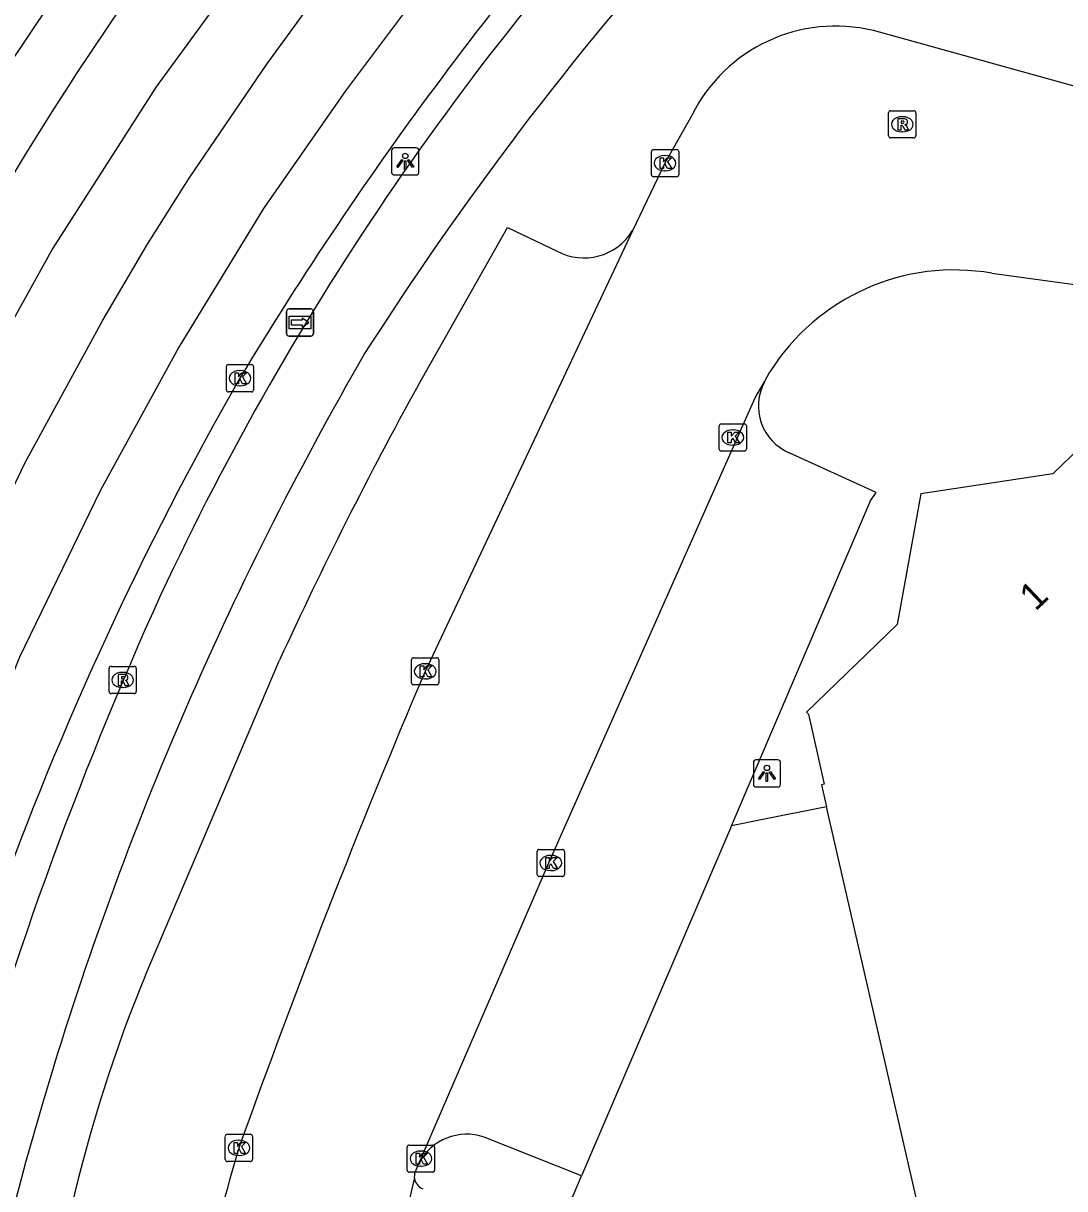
# Model space of a CAD drawing. Extents: x 160676 to 161153, y 383244 to 383713.
# Drawn here: x 160695.65 to 160733.93, y 383532.99 to 383575.83 of the extents above; entities that cross this region are included whole.
import ezdxf

# ---------------------------------------------------------------- set-up
doc = ezdxf.new("R2010")
doc.units = 0
for name, color, linetype in [('IMGEO_Fietspad_gesloten', 7, 'Continuous'), ('IMGEO_Kolk', 7, 'Continuous'), ('IMGEO_Lichtpunt', 7, 'Continuous'), ('IMGEO_Pand', 7, 'Continuous'), ('IMGEO_Pand_nummerreeks', 7, 'Continuous'), ('IMGEO_Parkeervlak_open', 7, 'Continuous'), ('IMGEO_Rijbaan_lokaal_gesloten', 7, 'Continuous'), ('IMGEO_Rijbaan_lokaal_open', 7, 'Continuous'), ('IMGEO_Rioolput', 7, 'Continuous'), ('IMGEO_Voetpad_open', 7, 'Continuous'), ('IMGEO_Wegwijzer', 7, 'Continuous')]:
    doc.layers.add(name, color=color, linetype=linetype)

msp = doc.modelspace()

# ---------------------------------------------------------------- linework, layer by layer
at = {"layer": 'IMGEO_Fietspad_gesloten'}
for centre, radius, start, end in [((160795.912, 383510.438), 105.044, 136.08487, 154.99624), ((160811.698, 383497.699), 122.747, 138.12959, 147.47881), ((160817.305, 383500.502), 126.082, 149.92333, 163.57354), ((160830.886, 383495.869), 142.908, 155.6296, 173.65091), ((160839.463, 383494.069), 149.155, 163.61031, 177.72109)]:
    msp.add_arc(centre, radius, start, end, dxfattribs=at)
at = {"layer": 'IMGEO_Kolk'}
for p, q in [((160718.741, 383570.266), (160718.741, 383571.118)), ((160718.816, 383571.192), (160719.668, 383571.192)), ((160719.742, 383571.118), (160719.742, 383570.266)), ((160719.229, 383570.972), (160719.254, 383570.972)), ((160719.668, 383570.192), (160718.816, 383570.192)), ((160719.252, 383570.412), (160719.227, 383570.412)), ((160703.116, 383562.359), (160703.116, 383563.211)), ((160703.191, 383563.285), (160704.043, 383563.285)), ((160703.604, 383563.065), (160703.629, 383563.065)), ((160704.117, 383563.211), (160704.117, 383562.359)), ((160703.627, 383562.505), (160703.602, 383562.505)), ((160704.043, 383562.285), (160703.191, 383562.285)), ((160721.232, 383560.182), (160721.232, 383561.034)), ((160721.307, 383561.108), (160722.159, 383561.108)), ((160721.72, 383560.888), (160721.745, 383560.888)), ((160722.233, 383561.034), (160722.233, 383560.182)), ((160721.743, 383560.328), (160721.718, 383560.328)), ((160722.159, 383560.108), (160721.307, 383560.108)), ((160709.925, 383551.583), (160709.925, 383552.435)), ((160710, 383552.509), (160710.852, 383552.509)), ((160710.413, 383552.289), (160710.438, 383552.289)), ((160710.926, 383552.435), (160710.926, 383551.583)), ((160710.852, 383551.509), (160710, 383551.509)), ((160710.436, 383551.729), (160710.411, 383551.729)), ((160714.542, 383544.536), (160714.542, 383545.388)), ((160714.617, 383545.462), (160715.469, 383545.462)), ((160715.543, 383545.388), (160715.543, 383544.536)), ((160715.03, 383545.242), (160715.055, 383545.242)), ((160715.469, 383544.462), (160714.617, 383544.462)), ((160715.053, 383544.682), (160715.028, 383544.682)), ((160703.078, 383534.06), (160703.078, 383534.912)), ((160703.153, 383534.986), (160704.005, 383534.986)), ((160703.566, 383534.766), (160703.591, 383534.766)), ((160704.079, 383534.912), (160704.079, 383534.06)), ((160703.589, 383534.206), (160703.564, 383534.206)), ((160709.767, 383533.666), (160709.767, 383534.518)), ((160709.842, 383534.592), (160710.694, 383534.592)), ((160710.255, 383534.372), (160710.28, 383534.372)), ((160710.768, 383534.518), (160710.768, 383533.666)), ((160704.005, 383533.986), (160703.153, 383533.986)), ((160710.278, 383533.812), (160710.253, 383533.812)), ((160710.694, 383533.592), (160709.842, 383533.592))]:
    msp.add_line(p, q, dxfattribs=at)
for points in [[(160718.741, 383570.266), (160718.741, 383571.118)], [(160718.816, 383571.192), (160719.668, 383571.192)], [(160719.742, 383571.118), (160719.742, 383570.266)], [(160719.062, 383570.892), (160719.185, 383570.892), (160719.185, 383570.741), (160719.315, 383570.892), (160719.479, 383570.892), (160719.333, 383570.741), (160719.486, 383570.492), (160719.334, 383570.492), (160719.249, 383570.656), (160719.185, 383570.589), (160719.185, 383570.492), (160719.062, 383570.492), (160719.062, 383570.892)], [(160719.668, 383570.192), (160718.816, 383570.192)], [(160703.116, 383562.359), (160703.116, 383563.211)], [(160703.191, 383563.285), (160704.043, 383563.285)], [(160703.437, 383562.985), (160703.56, 383562.985), (160703.56, 383562.834), (160703.69, 383562.985), (160703.854, 383562.985), (160703.708, 383562.834), (160703.861, 383562.585), (160703.709, 383562.585), (160703.624, 383562.749), (160703.56, 383562.682), (160703.56, 383562.585), (160703.437, 383562.585), (160703.437, 383562.985)], [(160704.117, 383563.211), (160704.117, 383562.359)], [(160704.043, 383562.285), (160703.191, 383562.285)], [(160721.232, 383560.182), (160721.232, 383561.034)], [(160721.307, 383561.108), (160722.159, 383561.108)], [(160721.553, 383560.808), (160721.676, 383560.808), (160721.676, 383560.657), (160721.806, 383560.808), (160721.97, 383560.808), (160721.824, 383560.657), (160721.977, 383560.408), (160721.825, 383560.408), (160721.74, 383560.572), (160721.676, 383560.505), (160721.676, 383560.408), (160721.553, 383560.408), (160721.553, 383560.808)], [(160722.233, 383561.034), (160722.233, 383560.182)], [(160722.159, 383560.108), (160721.307, 383560.108)], [(160709.925, 383551.583), (160709.925, 383552.435)], [(160710, 383552.509), (160710.852, 383552.509)], [(160710.246, 383552.209), (160710.369, 383552.209), (160710.369, 383552.058), (160710.499, 383552.209), (160710.663, 383552.209), (160710.517, 383552.058), (160710.67, 383551.809), (160710.518, 383551.809), (160710.433, 383551.973), (160710.369, 383551.906), (160710.369, 383551.809), (160710.246, 383551.809), (160710.246, 383552.209)], [(160710.926, 383552.435), (160710.926, 383551.583)], [(160710.852, 383551.509), (160710, 383551.509)], [(160714.542, 383544.536), (160714.542, 383545.388)], [(160714.617, 383545.462), (160715.469, 383545.462)], [(160715.543, 383545.388), (160715.543, 383544.536)], [(160714.863, 383545.162), (160714.986, 383545.162), (160714.986, 383545.011), (160715.116, 383545.162), (160715.28, 383545.162), (160715.134, 383545.011), (160715.287, 383544.762), (160715.135, 383544.762), (160715.05, 383544.926), (160714.986, 383544.859), (160714.986, 383544.762), (160714.863, 383544.762), (160714.863, 383545.162)], [(160715.469, 383544.462), (160714.617, 383544.462)], [(160703.078, 383534.06), (160703.078, 383534.912)], [(160703.153, 383534.986), (160704.005, 383534.986)], [(160703.399, 383534.686), (160703.522, 383534.686), (160703.522, 383534.535), (160703.652, 383534.686), (160703.816, 383534.686), (160703.67, 383534.535), (160703.823, 383534.286), (160703.671, 383534.286), (160703.586, 383534.45), (160703.522, 383534.383), (160703.522, 383534.286), (160703.399, 383534.286), (160703.399, 383534.686)], [(160704.079, 383534.912), (160704.079, 383534.06)], [(160709.767, 383533.666), (160709.767, 383534.518)], [(160709.842, 383534.592), (160710.694, 383534.592)], [(160710.088, 383534.292), (160710.211, 383534.292), (160710.211, 383534.141), (160710.341, 383534.292), (160710.505, 383534.292), (160710.359, 383534.141), (160710.512, 383533.892), (160710.36, 383533.892), (160710.275, 383534.056), (160710.211, 383533.989), (160710.211, 383533.892), (160710.088, 383533.892), (160710.088, 383534.292)], [(160710.768, 383534.518), (160710.768, 383533.666)], [(160704.005, 383533.986), (160703.153, 383533.986)], [(160710.694, 383533.592), (160709.842, 383533.592)]]:
    msp.add_lwpolyline(points, dxfattribs=at)
for centre, start, end in [((160718.818, 383571.116), 91.552, 178.448), ((160718.818, 383571.116), 91.552, 178.448), ((160719.666, 383571.116), 1.552, 88.448), ((160719.666, 383571.116), 1.552, 88.448), ((160718.818, 383570.268), 181.552, 268.448), ((160718.818, 383570.268), 181.552, 268.448), ((160719.666, 383570.268), 271.552, 358.448), ((160719.666, 383570.268), 271.552, 358.448), ((160703.193, 383563.209), 91.552, 178.448), ((160703.193, 383563.209), 91.552, 178.448), ((160704.041, 383563.209), 1.552, 88.448), ((160704.041, 383563.209), 1.552, 88.448), ((160703.193, 383562.361), 181.552, 268.448), ((160703.193, 383562.361), 181.552, 268.448), ((160704.041, 383562.361), 271.552, 358.448), ((160704.041, 383562.361), 271.552, 358.448), ((160721.309, 383561.032), 91.552, 178.448), ((160721.309, 383561.032), 91.552, 178.448), ((160722.157, 383561.032), 1.552, 88.448), ((160722.157, 383561.032), 1.552, 88.448), ((160721.309, 383560.184), 181.552, 268.448), ((160721.309, 383560.184), 181.552, 268.448), ((160722.157, 383560.184), 271.552, 358.448), ((160722.157, 383560.184), 271.552, 358.448), ((160710.002, 383552.433), 91.552, 178.448), ((160710.002, 383552.433), 91.552, 178.448), ((160710.85, 383552.433), 1.552, 88.448), ((160710.85, 383552.433), 1.552, 88.448), ((160710.002, 383551.585), 181.552, 268.448), ((160710.002, 383551.585), 181.552, 268.448), ((160710.85, 383551.585), 271.552, 358.448), ((160710.85, 383551.585), 271.552, 358.448), ((160714.619, 383545.386), 91.552, 178.448), ((160714.619, 383545.386), 91.552, 178.448), ((160715.467, 383545.386), 1.552, 88.448), ((160715.467, 383545.386), 1.552, 88.448), ((160714.619, 383544.538), 181.552, 268.448), ((160714.619, 383544.538), 181.552, 268.448), ((160715.467, 383544.538), 271.552, 358.448), ((160715.467, 383544.538), 271.552, 358.448), ((160703.155, 383534.91), 91.552, 178.448), ((160703.155, 383534.91), 91.552, 178.448), ((160704.003, 383534.91), 1.552, 88.448), ((160704.003, 383534.91), 1.552, 88.448), ((160709.844, 383534.516), 91.552, 178.448), ((160709.844, 383534.516), 91.552, 178.448), ((160710.692, 383534.516), 1.552, 88.448), ((160710.692, 383534.516), 1.552, 88.448), ((160703.155, 383534.062), 181.552, 268.448), ((160703.155, 383534.062), 181.552, 268.448), ((160704.003, 383534.062), 271.552, 358.448), ((160704.003, 383534.062), 271.552, 358.448), ((160709.844, 383533.668), 181.552, 268.448), ((160709.844, 383533.668), 181.552, 268.448), ((160710.692, 383533.668), 271.552, 358.448), ((160710.692, 383533.668), 271.552, 358.448)]:
    msp.add_arc(centre, 0.0765, start, end, dxfattribs=at)
for centre, major_axis, ratio, start_param, end_param in [((160719.228, 383570.692), (-0.387, 0.002), 0.722429, 4.712389, 7.853982), ((160719.253, 383570.692), (-0.39, 0.002), 0.717154, 1.570796, 4.712389), ((160703.603, 383562.785), (-0.387, 0.002), 0.722429, 4.712389, 7.853982), ((160703.628, 383562.785), (-0.39, 0.002), 0.717154, 1.570796, 4.712389), ((160721.719, 383560.608), (-0.387, 0.002), 0.722429, 4.712389, 7.853982), ((160721.744, 383560.608), (-0.39, 0.002), 0.717154, 1.570796, 4.712389), ((160710.412, 383552.009), (-0.387, 0.002), 0.722429, 4.712389, 7.853982), ((160710.437, 383552.009), (-0.39, 0.002), 0.717154, 1.570796, 4.712389), ((160715.029, 383544.962), (-0.387, 0.002), 0.722429, 4.712389, 7.853982), ((160715.054, 383544.962), (-0.39, 0.002), 0.717154, 1.570796, 4.712389), ((160703.565, 383534.486), (-0.387, 0.002), 0.722429, 4.712389, 7.853982), ((160703.59, 383534.486), (-0.39, 0.002), 0.717154, 1.570796, 4.712389), ((160710.254, 383534.092), (-0.387, 0.002), 0.722429, 4.712389, 7.853982), ((160710.279, 383534.092), (-0.39, 0.002), 0.717154, 1.570796, 4.712389)]:
    msp.add_ellipse(centre, major_axis=major_axis, ratio=ratio, start_param=start_param, end_param=end_param, dxfattribs=at)
at = {"layer": 'IMGEO_Lichtpunt'}
for p, q in [((160709.192, 383571.161), (160709.192, 383570.354)), ((160709.192, 383571.161), (160709.192, 383570.354)), ((160710.094, 383571.256), (160709.286, 383571.256)), ((160710.094, 383571.256), (160709.286, 383571.256)), ((160710.188, 383570.354), (160710.188, 383571.161)), ((160710.188, 383570.354), (160710.188, 383571.161)), ((160709.286, 383570.26), (160710.094, 383570.26)), ((160709.286, 383570.26), (160710.094, 383570.26)), ((160723.39, 383548.756), (160722.582, 383548.756)), ((160723.39, 383548.756), (160722.582, 383548.756)), ((160722.488, 383548.661), (160722.488, 383547.854)), ((160722.488, 383548.661), (160722.488, 383547.854)), ((160723.484, 383547.854), (160723.484, 383548.661)), ((160723.484, 383547.854), (160723.484, 383548.661)), ((160722.582, 383547.76), (160723.39, 383547.76)), ((160722.582, 383547.76), (160723.39, 383547.76))]:
    msp.add_line(p, q, dxfattribs=at)
for points in [[(160709.566, 383570.825), (160709.605, 383570.797), (160709.417, 383570.535), (160709.379, 383570.562), (160709.566, 383570.825)], [(160709.668, 383570.777), (160709.715, 383570.777), (160709.715, 383570.455), (160709.668, 383570.455), (160709.668, 383570.777)], [(160709.778, 383570.797), (160709.816, 383570.824), (160710.003, 383570.562), (160709.964, 383570.534), (160709.778, 383570.797)], [(160722.862, 383548.325), (160722.901, 383548.297), (160722.713, 383548.035), (160722.675, 383548.062), (160722.862, 383548.325)], [(160723.074, 383548.297), (160723.112, 383548.324), (160723.299, 383548.062), (160723.26, 383548.034), (160723.074, 383548.297)], [(160722.964, 383548.277), (160723.011, 383548.277), (160723.011, 383547.955), (160722.964, 383547.955), (160722.964, 383548.277)]]:
    msp.add_lwpolyline(points, dxfattribs=at)
for centre in [(160709.691, 383570.959), (160722.987, 383548.459)]:
    msp.add_circle(centre, 0.0994, dxfattribs=at)
for centre, start, end in [((160709.286, 383571.161), 90, 180), ((160709.286, 383571.161), 90, 180), ((160710.094, 383571.161), 0, 90), ((160710.094, 383571.161), 0, 90), ((160709.286, 383570.354), 180, 270), ((160709.286, 383570.354), 180, 270), ((160710.094, 383570.354), 270, 0), ((160710.094, 383570.354), 270, 360), ((160722.582, 383548.661), 90, 180), ((160722.582, 383548.661), 90, 180), ((160723.39, 383548.661), 0, 90), ((160723.39, 383548.661), 0, 90), ((160722.582, 383547.854), 180, 270), ((160722.582, 383547.854), 180, 270), ((160723.39, 383547.854), 270, 0), ((160723.39, 383547.854), 270, 360)]:
    msp.add_arc(centre, 0.0946, start, end, dxfattribs=at)
at = {"layer": 'IMGEO_Pand'}
for points in [[(160736.867, 383562.513), (160734.183, 383559.937), (160733.494, 383559.276), (160728.647, 383558.534), (160727.771, 383553.734), (160724.44, 383550.502), (160724.51, 383550.431), (160725.086, 383547.856), (160724.989, 383547.833), (160725.173, 383547.028)], [(160737.721, 383492.328), (160725.173, 383547.028)]]:
    msp.add_lwpolyline(points, dxfattribs=at)
at = {"layer": 'IMGEO_Parkeervlak_open'}
msp.add_lwpolyline([(160721.686, 383546.332), (160716.176, 383533.454)], dxfattribs=at)
at = {"layer": 'IMGEO_Rijbaan_lokaal_gesloten'}
for points in [[(160695.008, 383574.126), (160700.015, 383581.605), (160701.217, 383583.225), (160702.452, 383584.824), (160718.729, 383604.358)], [(160720.463, 383602.931), (160704.514, 383583.748), (160702.967, 383581.799), (160701.503, 383579.813), (160697.601, 383573.971)], [(160723.044, 383600.836), (160719.324, 383596.439), (160713.063, 383589.27), (160709.696, 383585.215), (160705.6, 383580.218), (160702.963, 383576.838), (160700.534, 383573.501), (160696.741, 383567.566), (160694.147, 383562.923), (160691.409, 383557.397), (160688.975, 383551.769), (160686.454, 383545.185), (160684.145, 383538.275), (160682.371, 383532.368), (160681.16, 383527.53), (160680.501, 383524.333), (160679.874, 383520.258), (160679.388, 383515.338), (160678.873, 383508.063), (160678.616, 383502.924)], [(160685.454, 383532.715), (160686.021, 383534.678), (160688.067, 383541.099), (160690.125, 383546.785), (160692.81, 383553.46), (160693.996, 383556.078), (160695.715, 383559.665), (160698.57, 383564.917), (160700.214, 383567.717), (160701.75, 383570.142), (160704.599, 383574.336), (160706.977, 383577.606), (160709.977, 383581.462), (160714.314, 383586.666), (160720.291, 383593.191), (160725.485, 383598.855)], [(160727.682, 383597.073), (160717.292, 383585.599), (160710.987, 383578.024), (160707.499, 383573.354), (160704.487, 383569.021), (160701.37, 383563.93), (160698.475, 383558.64), (160695.509, 383552.532), (160692.543, 383545.152), (160690.79, 383540.075), (160689.355, 383535.536), (160687.563, 383528.543), (160686.35, 383522.561), (160685.459, 383515.912), (160684.867, 383507.93), (160684.757, 383502.656), (160684.835, 383499.113), (160684.974, 383496.66)]]:
    msp.add_lwpolyline(points, dxfattribs=at)
for centre, radius, start, end in [((160817.455, 383494.338), 132.835, 137.49629, 148.98372), ((160804.362, 383504.18), 127.549, 146.82685, 161.20972), ((160810.136, 383501.829), 122.732, 150.22022, 160.29522)]:
    msp.add_arc(centre, radius, start, end, dxfattribs=at)
at = {"layer": 'IMGEO_Rijbaan_lokaal_open'}
for points in [[(160736.61, 383572.879), (160735.379, 383573.223), (160726.9, 383575.565)], [(160720.237, 383572.472), (160719.237, 383570.693), (160718.039, 383568.205)], [(160718.039, 383568.205), (160710.422, 383552.008)], [(160731.259, 383566.644), (160735.719, 383566.037)], [(160722.893, 383562.651), (160723.098, 383563.016)], [(160710.198, 383533.933), (160714.965, 383544.967), (160722.4, 383561.708), (160722.559, 383562.066), (160722.893, 383562.651)], [(160710.057, 383533.594), (160710.198, 383533.933)], [(160708.388, 383526.243), (160710.033, 383533.347)]]:
    msp.add_lwpolyline(points, dxfattribs=at)
for centre, radius, start, end in [((160725.51, 383569.835), 5.896, 76.3684, 153.4335), ((160729.869, 383558.778), 7.988, 79.9801, 147.9553), ((161001.115, 383428.408), 315.879, 156.96532, 160.37851), ((160756.116, 383518.41), 54.94, 162.9902, 176.0978), ((160710.485, 383533.428), 0.46, 158.7883, 190.1122), ((160710.493, 383533.428), 0.467, 189.993, 250.9206)]:
    msp.add_arc(centre, radius, start, end, dxfattribs=at)
at = {"layer": 'IMGEO_Rioolput'}
for p, q in [((160727.459, 383571.696), (160727.459, 383572.548)), ((160727.534, 383572.622), (160728.386, 383572.622)), ((160727.947, 383572.402), (160727.972, 383572.402)), ((160728.46, 383572.548), (160728.46, 383571.696)), ((160728.386, 383571.622), (160727.534, 383571.622)), ((160727.97, 383571.842), (160727.945, 383571.842)), ((160698.879, 383552.192), (160699.731, 383552.192)), ((160698.804, 383551.266), (160698.804, 383552.118)), ((160699.292, 383551.972), (160699.317, 383551.972)), ((160699.805, 383552.118), (160699.805, 383551.266)), ((160699.315, 383551.412), (160699.29, 383551.412)), ((160699.731, 383551.192), (160698.879, 383551.192))]:
    msp.add_line(p, q, dxfattribs=at)
for points in [[(160727.459, 383571.696), (160727.459, 383572.548)], [(160727.534, 383572.622), (160728.386, 383572.622)], [(160728.048, 383572.32), (160727.796, 383572.322), (160727.796, 383571.922)], [(160728.46, 383572.548), (160728.46, 383571.696)], [(160727.796, 383571.922), (160727.92, 383571.922), (160727.92, 383572.084), (160727.931, 383572.084)], [(160727.974, 383572.241), (160727.92, 383572.241), (160727.92, 383572.16)], [(160727.92, 383572.16), (160727.972, 383572.16)], [(160727.978, 383572.055), (160728.049, 383571.922), (160728.189, 383571.922), (160728.124, 383572.048)], [(160728.386, 383571.622), (160727.534, 383571.622)], [(160698.879, 383552.192), (160699.731, 383552.192)], [(160698.804, 383551.266), (160698.804, 383552.118)], [(160699.393, 383551.89), (160699.141, 383551.892), (160699.141, 383551.492)], [(160699.319, 383551.811), (160699.265, 383551.811), (160699.265, 383551.73)], [(160699.805, 383552.118), (160699.805, 383551.266)], [(160699.141, 383551.492), (160699.265, 383551.492), (160699.265, 383551.654), (160699.276, 383551.654)], [(160699.265, 383551.73), (160699.317, 383551.73)], [(160699.323, 383551.625), (160699.394, 383551.492), (160699.534, 383551.492), (160699.469, 383551.618)], [(160699.731, 383551.192), (160698.879, 383551.192)]]:
    msp.add_lwpolyline(points, dxfattribs=at)
for centre, radius, start, end in [((160727.536, 383572.546), 0.0765, 91.552, 178.448), ((160727.536, 383572.546), 0.0765, 91.552, 178.448), ((160728.047, 383572.21), 0.109, 350.3612, 89.416), ((160728.384, 383572.546), 0.0765, 1.552, 88.448), ((160728.384, 383572.546), 0.0765, 1.552, 88.448), ((160727.93, 383572.031), 0.0533, 26.0293, 88.6989), ((160727.956, 383572.349), 0.19, 274.7715, 282.9687), ((160727.98, 383572.145), 0.0964, 77.0061, 93.1865), ((160727.994, 383572.202), 0.0378, 276.6634, 79.6772), ((160728.045, 383572.21), 0.112, 277.5842, 350.9817), ((160728.029, 383571.995), 0.108, 29.5134, 73.7905), ((160727.536, 383571.698), 0.0765, 181.552, 268.448), ((160727.536, 383571.698), 0.0765, 181.552, 268.448), ((160728.384, 383571.698), 0.0765, 271.552, 358.448), ((160728.384, 383571.698), 0.0765, 271.552, 358.448), ((160698.881, 383552.116), 0.0765, 91.552, 178.448), ((160698.881, 383552.116), 0.0765, 91.552, 178.448), ((160699.729, 383552.116), 0.0765, 1.552, 88.448), ((160699.729, 383552.116), 0.0765, 1.552, 88.448), ((160699.325, 383551.715), 0.0964, 77.0061, 93.1865), ((160699.339, 383551.772), 0.0378, 276.6634, 79.6772), ((160699.392, 383551.78), 0.109, 350.3612, 89.416), ((160699.39, 383551.78), 0.112, 277.5842, 350.9817), ((160699.275, 383551.601), 0.0533, 26.0293, 88.6989), ((160699.301, 383551.919), 0.19, 274.7715, 282.9687), ((160699.374, 383551.565), 0.108, 29.5134, 73.7905), ((160698.881, 383551.268), 0.0765, 181.552, 268.448), ((160698.881, 383551.268), 0.0765, 181.552, 268.448), ((160699.729, 383551.268), 0.0765, 271.552, 358.448), ((160699.729, 383551.268), 0.0765, 271.552, 358.448)]:
    msp.add_arc(centre, radius, start, end, dxfattribs=at)
for centre, major_axis, ratio, start_param, end_param in [((160727.946, 383572.122), (-0.387, 0.002), 0.722429, 4.712389, 7.853982), ((160727.971, 383572.122), (-0.39, 0.002), 0.717154, 1.570796, 4.712389), ((160699.291, 383551.692), (-0.387, 0.002), 0.722429, 4.712389, 7.853982), ((160699.316, 383551.692), (-0.39, 0.002), 0.717154, 1.570796, 4.712389)]:
    msp.add_ellipse(centre, major_axis=major_axis, ratio=ratio, start_param=start_param, end_param=end_param, dxfattribs=at)
at = {"layer": 'IMGEO_Voetpad_open'}
for points in [[(160710.163, 383562.52), (160713.447, 383568.327), (160715.275, 383567.455)], [(160721.686, 383546.332), (160726.796, 383558.275), (160727.001, 383558.583), (160723.807, 383560.045)], [(160700.144, 383540.842), (160705.074, 383552.423)], [(160725.173, 383547.028), (160722.775, 383546.549), (160721.686, 383546.332)], [(160716.176, 383533.454), (160712.593, 383534.884)], [(160720.463, 383529.159), (160715.345, 383531.511), (160716.176, 383533.454)]]:
    msp.add_lwpolyline(points, dxfattribs=at)
for centre, radius, start, end in [((160716.259, 383569.295), 2.087, 241.8499, 328.5129), ((160845.414, 383488.021), 154.412, 151.15315, 155.34963), ((160724.548, 383561.768), 1.876, 151.9167, 246.7378), ((160750.842, 383519.973), 54.825, 157.6263, 176.4844), ((160711.955, 383533), 1.989, 71.2768, 152.037)]:
    msp.add_arc(centre, radius, start, end, dxfattribs=at)
at = {"layer": 'IMGEO_Wegwijzer'}
for p, q in [((160705.327, 383564.432), (160705.327, 383565.232)), ((160705.327, 383565.232), (160705.327, 383564.432)), ((160705.427, 383565.332), (160706.217, 383565.332)), ((160706.217, 383565.332), (160705.427, 383565.332)), ((160706.317, 383565.232), (160706.317, 383564.432)), ((160706.317, 383564.432), (160706.317, 383565.232)), ((160706.217, 383564.332), (160705.427, 383564.332)), ((160705.427, 383564.332), (160706.217, 383564.332))]:
    msp.add_line(p, q, dxfattribs=at)
for points in [[(160705.428, 383565.064), (160706.216, 383565.064), (160706.216, 383564.6), (160705.428, 383564.6), (160705.428, 383565.064)], [(160705.493, 383564.916), (160705.493, 383564.832), (160705.493, 383564.748), (160705.904, 383564.748), (160705.904, 383564.665), (160706.151, 383564.832), (160705.904, 383564.999), (160705.904, 383564.916), (160705.493, 383564.916)]]:
    msp.add_lwpolyline(points, dxfattribs=at)
for centre, start, end in [((160705.427, 383565.232), 90, 180), ((160705.427, 383565.232), 90, 180), ((160706.217, 383565.232), 0, 90), ((160706.217, 383565.232), 360, 90), ((160705.427, 383564.432), 180, 270), ((160705.427, 383564.432), 180, 270), ((160706.217, 383564.432), 270, 0), ((160706.217, 383564.432), 270, 0)]:
    msp.add_arc(centre, 0.1, start, end, dxfattribs=at)

# ---------------------------------------------------------------- texts
at = {"layer": 'IMGEO_Pand_nummerreeks'}
msp.add_text('1', height=1, rotation=43.4588, dxfattribs=at).set_placement((160732.855, 383554.194))

doc.saveas('drawing.dxf')
